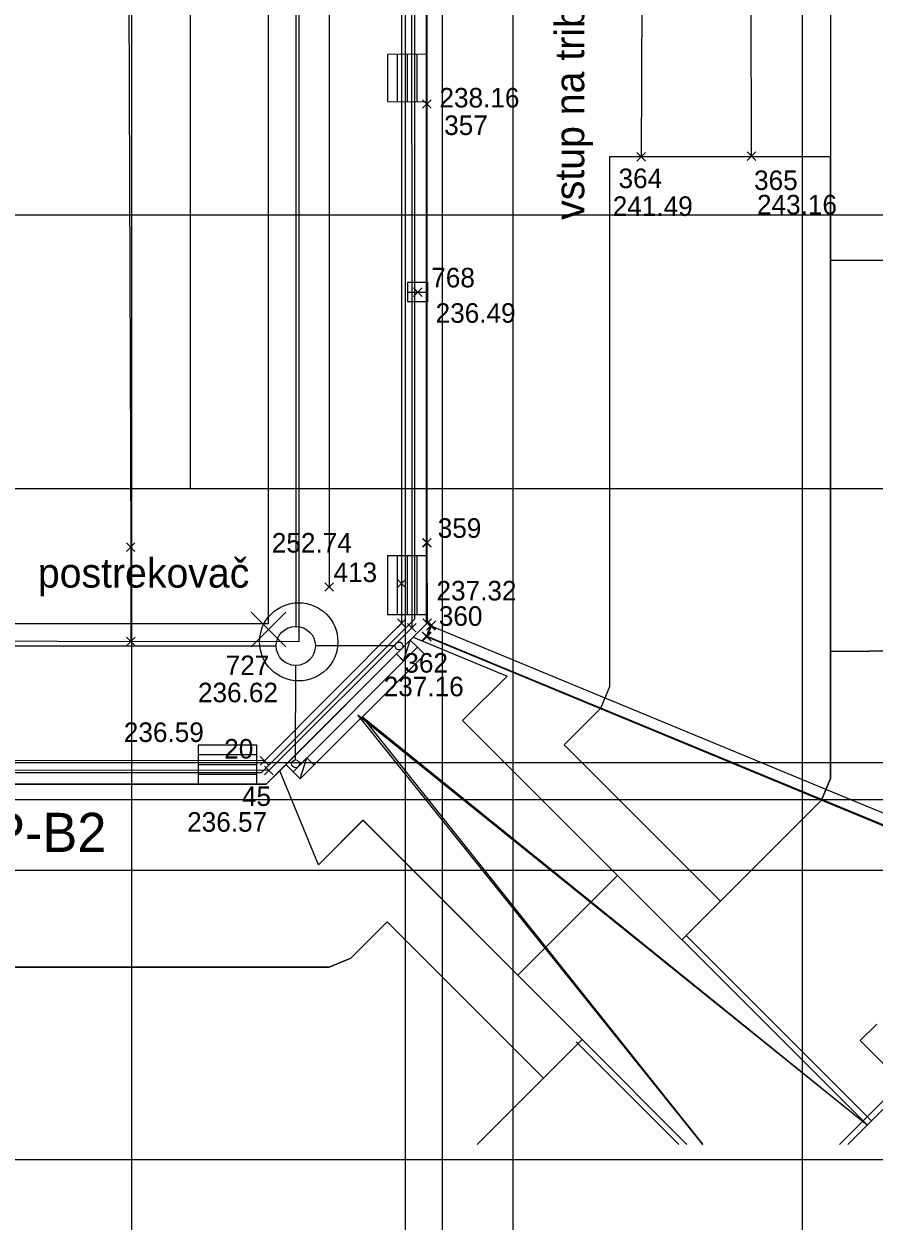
# Model space of a CAD drawing. Extents: x -264205 to -263659, y -1242401 to -1242060.
# Drawn here: x -263822.21 to -263800.48, y -1242235.6 to -1242205 of the extents above; entities that cross this region are included whole.
import ezdxf

# ---------------------------------------------------------------- set-up
doc = ezdxf.new("R2010")
doc.units = 0
for name, color, linetype in [('BOD_CISLO', 7, 'Continuous'), ('BOD_SYMBOL', 7, 'Continuous'), ('BOD_VYSKA', 7, 'Continuous'), ('KFA_SO_10-1_DRENAZNY_SYSTEM_IHRISKA', 7, 'Continuous'), ('KFA_SO_10-1_OBRUBNIKY_IHRISKO', 7, 'Continuous'), ('KFA_SO_10-1_POSTREKOVACE', 7, 'Continuous'), ('KFA_SO_10-1_STRECHY', 7, 'Continuous'), ('KFA_SO_10-1_SVETELNE_VEZE', 7, 'Continuous'), ('KFA_SO_10-1_TRIBUNA_C_OBVOD', 7, 'Continuous'), ('KFA_SO_10-1_VPUST_STADION_POKLOP', 7, 'Continuous'), ('KFA_SO_10-1_VSTUPY_TRIBUNA_C', 7, 'Continuous'), ('KFA_SO_10-1_ZABRADLIE_STADION', 7, 'Continuous'), ('KFA_SO_40-2-II_DAZDOVA_KANALIZACIA', 7, 'Continuous'), ('OBRUBNIKY_KOMUNIKACIE_PROJEKT', 7, 'Continuous'), ('OSI_STAVBY_KFA', 7, 'Continuous'), ('POPIS', 7, 'Continuous'), ('SITUACIA_DSP_2D', 7, 'Continuous')]:
    doc.layers.add(name, color=color, linetype=linetype)

msp = doc.modelspace()

# ---------------------------------------------------------------- linework, layer by layer
at = {"layer": 'BOD_SYMBOL'}
for p, q in [((-263812.024, -1242207.154), (-263811.802, -1242206.933)), ((-263811.802, -1242207.154), (-263812.024, -1242206.933)), ((-263806.545, -1242208.508), (-263806.323, -1242208.286)), ((-263806.323, -1242208.508), (-263806.545, -1242208.286)), ((-263806.541, -1242208.504), (-263806.32, -1242208.282)), ((-263806.32, -1242208.504), (-263806.541, -1242208.282)), ((-263803.72, -1242208.488), (-263803.5, -1242208.266)), ((-263803.5, -1242208.488), (-263803.72, -1242208.266)), ((-263812.257, -1242211.961), (-263812.035, -1242211.741)), ((-263812.035, -1242211.961), (-263812.257, -1242211.741)), ((-263819.595, -1242218.478), (-263819.375, -1242218.257)), ((-263819.375, -1242218.478), (-263819.595, -1242218.257)), ((-263812.02, -1242218.367), (-263811.799, -1242218.147)), ((-263811.799, -1242218.367), (-263812.02, -1242218.147)), ((-263812.019, -1242218.369), (-263811.799, -1242218.147)), ((-263811.799, -1242218.369), (-263812.019, -1242218.147)), ((-263812.67, -1242219.409), (-263812.448, -1242219.188)), ((-263812.448, -1242219.409), (-263812.67, -1242219.188)), ((-263814.522, -1242219.499), (-263814.301, -1242219.279)), ((-263814.301, -1242219.499), (-263814.522, -1242219.279)), ((-263816.072, -1242220.589), (-263815.851, -1242220.367)), ((-263815.851, -1242220.589), (-263816.072, -1242220.367)), ((-263812.667, -1242220.421), (-263812.446, -1242220.2)), ((-263812.446, -1242220.421), (-263812.667, -1242220.2)), ((-263812.406, -1242220.546), (-263812.185, -1242220.326)), ((-263812.185, -1242220.546), (-263812.406, -1242220.326)), ((-263812.018, -1242220.426), (-263811.796, -1242220.204)), ((-263811.796, -1242220.426), (-263812.018, -1242220.204)), ((-263811.921, -1242220.497), (-263811.7, -1242220.275)), ((-263811.7, -1242220.497), (-263811.921, -1242220.275)), ((-263811.904, -1242220.478), (-263811.682, -1242220.258)), ((-263811.682, -1242220.478), (-263811.904, -1242220.258)), ((-263819.59, -1242220.896), (-263819.369, -1242220.674)), ((-263819.369, -1242220.896), (-263819.59, -1242220.674)), ((-263812.03, -1242220.758), (-263811.808, -1242220.536)), ((-263811.808, -1242220.758), (-263812.03, -1242220.536)), ((-263812.024, -1242220.774), (-263811.802, -1242220.552)), ((-263811.802, -1242220.774), (-263812.024, -1242220.552)), ((-263816.175, -1242223.941), (-263815.954, -1242223.72)), ((-263815.954, -1242223.941), (-263816.175, -1242223.72)), ((-263816.066, -1242224.191), (-263815.845, -1242223.97)), ((-263815.845, -1242224.191), (-263816.066, -1242223.97))]:
    msp.add_line(p, q, dxfattribs=at)
at = {"layer": 'KFA_SO_10-1_DRENAZNY_SYSTEM_IHRISKA'}
msp.add_line((-263819.485, -1242218.367), (-263819.48, -1242220.785), dxfattribs=at)
msp.add_lwpolyline([(-263819.808, -1242114.324), (-263819.677, -1242164.565), (-263819.485, -1242218.367)], dxfattribs=at)
at = {"layer": 'KFA_SO_10-1_OBRUBNIKY_IHRISKO'}
msp.add_line((-263812.559, -1242219.298), (-263812.557, -1242220.31), dxfattribs=at)
for points in [[(-263812.554, -1242108.944), (-263812.55, -1242123.834), (-263812.543, -1242140.463), (-263812.561, -1242166.622), (-263812.562, -1242195.738), (-263812.559, -1242219.298)], [(-263812.302, -1242108.944), (-263812.301, -1242123.86), (-263812.298, -1242140.481), (-263812.303, -1242166.591), (-263812.301, -1242195.713), (-263812.296, -1242220.436)], [(-263812.296, -1242220.436), (-263815.955, -1242224.08), (-263837.958, -1242224.073), (-263865.382, -1242224.053), (-263888.004, -1242224.071), (-263891.613, -1242220.398)], [(-263812.557, -1242220.31), (-263816.064, -1242223.83), (-263837.963, -1242223.813), (-263865.333, -1242223.805), (-263887.909, -1242223.807), (-263891.344, -1242220.296)]]:
    msp.add_lwpolyline(points, dxfattribs=at)
at = {"layer": 'KFA_SO_10-1_POSTREKOVACE'}
for p, q in [((-263816.403, -1242220.92), (-263815.519, -1242220.036)), ((-263815.519, -1242220.92), (-263816.403, -1242220.036))]:
    msp.add_line(p, q, dxfattribs=at)
at = {"layer": 'KFA_SO_10-1_STRECHY'}
msp.add_line((-263814.432, -1242109.405), (-263814.411, -1242219.389), dxfattribs=at)
at = {"layer": 'KFA_SO_10-1_TRIBUNA_C_OBVOD'}
msp.add_line((-263795.286, -1242227.548), (-263811.913, -1242220.663), dxfattribs=at)
msp.add_lwpolyline([(-263811.9, -1242108.121), (-263811.778, -1242108.42), (-263811.904, -1242108.455), (-263811.9, -1242110.523), (-263811.9, -1242110.524), (-263811.903, -1242123.046), (-263811.913, -1242144.045), (-263811.917, -1242165.045), (-263811.915, -1242186.053), (-263811.913, -1242207.043), (-263811.91, -1242218.257), (-263811.909, -1242218.258), (-263811.907, -1242220.315), (-263811.793, -1242220.368), (-263811.913, -1242220.663)], dxfattribs=at)
at = {"layer": 'KFA_SO_10-1_VPUST_STADION_POKLOP'}
msp.add_line((-263812.146, -1242211.851), (-263812.146, -1242211.851), dxfattribs=at)
msp.add_lwpolyline([(-263812.396, -1242211.851), (-263812.396, -1242211.601), (-263811.896, -1242211.601), (-263811.896, -1242212.101), (-263812.396, -1242212.101), (-263812.396, -1242211.851), (-263811.896, -1242211.851)], dxfattribs=at)
at = {"layer": 'KFA_SO_10-1_VSTUPY_TRIBUNA_C'}
msp.add_line((-263806.413, -1242204.348), (-263806.434, -1242208.397), dxfattribs=at)
msp.add_lwpolyline([(-263806.434, -1242208.397), (-263806.431, -1242208.393), (-263803.61, -1242208.377), (-263803.618, -1242204.362), (-263806.41, -1242204.343), (-263806.413, -1242204.348)], dxfattribs=at)
at = {"layer": 'KFA_SO_10-1_ZABRADLIE_STADION'}
msp.add_line((-263796.638, -1242226.962), (-263811.919, -1242220.647), dxfattribs=at)
msp.add_lwpolyline([(-263811.919, -1242220.647), (-263811.811, -1242220.386), (-263796.524, -1242226.704), (-263795.888, -1242226.969), (-263796.004, -1242227.229), (-263796.638, -1242226.962)], dxfattribs=at)
at = {"layer": 'KFA_SO_40-2-II_DAZDOVA_KANALIZACIA'}
msp.add_lwpolyline([(-263814.907, -1242107.856), (-263815.198, -1242164.443), (-263815.189, -1242220.791), (-263852.152, -1242220.736), (-263888.701, -1242220.786), (-263906.731, -1242239.259)], dxfattribs=at)
msp.add_circle((-263815.189, -1242220.791), 1, dxfattribs=at)
at = {"layer": 'OBRUBNIKY_KOMUNIKACIE_PROJEKT'}
for p, q in [((-263801.593, -1242104.482), (-263801.593, -1242224.282)), ((-263815.675, -1242224.088), (-263812.262, -1242220.675)), ((-263812.262, -1242220.675), (-263809.863, -1242221.669)), ((-263809.863, -1242221.669), (-263810.999, -1242222.806)), ((-263804.857, -1242233.636), (-263813.678, -1242222.657)), ((-263813.678, -1242222.657), (-263800.652, -1242233.141)), ((-263810.999, -1242222.806), (-263805.392, -1242228.407)), ((-263814.681, -1242226.488), (-263815.675, -1242224.088)), ((-263801.593, -1242224.282), (-263801.824, -1242224.838)), ((-263801.824, -1242224.838), (-263805.392, -1242228.407)), ((-263813.544, -1242225.352), (-263814.681, -1242226.488)), ((-263807.941, -1242230.956), (-263813.544, -1242225.352)), ((-263794.893, -1242227.382), (-263801.147, -1242233.636)), ((-263805.283, -1242228.297), (-263800.546, -1242233.035)), ((-263805.389, -1242228.403), (-263800.652, -1242233.141)), ((-263807.941, -1242230.956), (-263810.622, -1242233.636)), ((-263808.093, -1242231.016), (-263805.473, -1242233.636)), ((-263807.987, -1242230.91), (-263805.261, -1242233.636))]:
    msp.add_line(p, q, dxfattribs=at)
at = {"layer": 'OSI_STAVBY_KFA'}
for p, q in [((-263819.468, -1242083.237), (-263819.468, -1242246.707)), ((-263812.468, -1242083.237), (-263812.468, -1242246.707)), ((-263811.518, -1242083.237), (-263811.518, -1242246.707)), ((-263809.718, -1242083.237), (-263809.718, -1242246.707)), ((-263802.318, -1242083.237), (-263802.318, -1242246.707)), ((-263792.653, -1242209.882), (-263909.343, -1242209.882)), ((-263792.653, -1242216.882), (-263911.523, -1242216.882)), ((-263792.653, -1242223.882), (-263911.523, -1242223.882)), ((-263792.653, -1242224.832), (-263911.523, -1242224.832)), ((-263792.653, -1242226.632), (-263911.523, -1242226.632)), ((-263792.653, -1242234.032), (-263911.523, -1242234.032))]:
    msp.add_line(p, q, dxfattribs=at)
at = {"layer": 'SITUACIA_DSP_2D'}
for p, q in [((-263801.593, -1242104.482), (-263801.593, -1242224.282)), ((-263815.968, -1242108.434), (-263815.968, -1242220.33)), ((-263811.918, -1242108.434), (-263811.918, -1242220.33)), ((-263811.918, -1242220.33), (-263811.918, -1242108.434)), ((-263812.218, -1242220.206), (-263812.218, -1242108.558)), ((-263817.968, -1242111.882), (-263817.968, -1242216.882)), ((-263815.263, -1242164.687), (-263815.263, -1242220.396)), ((-263811.924, -1242205.773), (-263812.918, -1242205.782)), ((-263812.918, -1242205.782), (-263812.918, -1242206.982)), ((-263812.668, -1242205.782), (-263812.668, -1242206.982)), ((-263812.418, -1242205.782), (-263812.418, -1242206.982)), ((-263812.168, -1242205.782), (-263812.168, -1242206.982)), ((-263812.918, -1242206.982), (-263811.924, -1242206.991)), ((-263807.243, -1242208.394), (-263807.243, -1242221.942)), ((-263801.593, -1242208.394), (-263807.243, -1242208.394)), ((-263801.593, -1242208.394), (-263807.243, -1242208.394)), ((-263807.243, -1242208.394), (-263807.243, -1242221.942)), ((-263801.593, -1242224.282), (-263801.593, -1242208.394)), ((-263801.593, -1242224.282), (-263801.593, -1242208.394)), ((-263801.593, -1242211.032), (-263800.593, -1242211.032)), ((-263800.593, -1242211.032), (-263793.136, -1242211.032)), ((-263817.968, -1242216.882), (-263885.968, -1242216.882)), ((-263811.939, -1242218.592), (-263812.918, -1242218.592)), ((-263812.918, -1242218.592), (-263812.918, -1242220.092)), ((-263812.668, -1242218.592), (-263812.668, -1242220.092)), ((-263812.418, -1242218.592), (-263812.418, -1242220.092)), ((-263812.168, -1242218.592), (-263812.168, -1242220.092)), ((-263812.918, -1242220.092), (-263811.918, -1242220.092)), ((-263815.968, -1242220.33), (-263887.968, -1242220.33)), ((-263816.144, -1242224.132), (-263812.218, -1242220.206)), ((-263816.02, -1242224.432), (-263811.918, -1242220.33)), ((-263811.918, -1242220.33), (-263812.262, -1242220.675)), ((-263815.675, -1242224.088), (-263812.262, -1242220.675)), ((-263812.262, -1242220.675), (-263809.862, -1242221.669)), ((-263812.262, -1242220.675), (-263809.863, -1242221.669)), ((-263851.668, -1242220.896), (-263815.763, -1242220.896)), ((-263815.516, -1242223.929), (-263812.335, -1242220.747)), ((-263815.334, -1242224.112), (-263812.152, -1242220.929)), ((-263812.725, -1242220.896), (-263814.763, -1242220.896)), ((-263812.506, -1242221.283), (-263812.335, -1242220.747)), ((-263812.151, -1242220.931), (-263812.335, -1242220.747)), ((-263811.968, -1242221.113), (-263812.152, -1242220.929)), ((-263801.593, -1242221.032), (-263800.593, -1242221.032)), ((-263788.893, -1242221.032), (-263800.593, -1242221.032)), ((-263811.968, -1242221.113), (-263815.15, -1242224.295)), ((-263812.504, -1242221.284), (-263812.688, -1242221.101)), ((-263815.27, -1242223.809), (-263815.264, -1242221.396)), ((-263809.862, -1242221.669), (-263810.999, -1242222.806)), ((-263809.863, -1242221.669), (-263810.999, -1242222.806)), ((-263807.243, -1242221.942), (-263807.472, -1242222.496)), ((-263807.243, -1242221.942), (-263807.472, -1242222.496)), ((-263807.472, -1242222.496), (-263808.4, -1242223.424)), ((-263807.472, -1242222.496), (-263808.4, -1242223.424)), ((-263804.844, -1242233.636), (-263813.559, -1242222.704)), ((-263813.559, -1242222.704), (-263800.652, -1242233.141)), ((-263810.999, -1242222.806), (-263807.039, -1242226.765)), ((-263810.999, -1242222.806), (-263805.392, -1242228.407)), ((-263816.259, -1242223.432), (-263817.757, -1242223.432)), ((-263817.757, -1242223.432), (-263817.757, -1242224.432)), ((-263816.259, -1242224.432), (-263816.259, -1242223.432)), ((-263808.4, -1242223.424), (-263804.405, -1242227.419)), ((-263808.4, -1242223.424), (-263804.405, -1242227.419)), ((-263816.259, -1242223.682), (-263817.757, -1242223.682)), ((-263815.15, -1242224.295), (-263814.98, -1242223.758)), ((-263814.797, -1242223.942), (-263814.98, -1242223.758)), ((-263816.259, -1242223.932), (-263817.757, -1242223.932)), ((-263815.675, -1242224.088), (-263816.02, -1242224.432)), ((-263814.681, -1242226.488), (-263815.675, -1242224.088)), ((-263814.681, -1242226.488), (-263815.675, -1242224.088)), ((-263815.333, -1242224.113), (-263815.516, -1242223.929)), ((-263887.792, -1242224.132), (-263816.144, -1242224.132)), ((-263816.259, -1242224.182), (-263817.757, -1242224.182)), ((-263815.15, -1242224.295), (-263815.334, -1242224.112)), ((-263801.593, -1242224.282), (-263801.824, -1242224.838)), ((-263801.822, -1242224.837), (-263801.593, -1242224.282)), ((-263801.822, -1242224.837), (-263801.593, -1242224.282)), ((-263816.02, -1242224.432), (-263887.916, -1242224.432)), ((-263887.916, -1242224.432), (-263816.02, -1242224.432)), ((-263801.824, -1242224.838), (-263805.392, -1242228.407)), ((-263804.405, -1242227.419), (-263801.822, -1242224.837)), ((-263804.405, -1242227.419), (-263801.822, -1242224.837)), ((-263813.545, -1242225.351), (-263814.681, -1242226.488)), ((-263813.544, -1242225.352), (-263814.681, -1242226.488)), ((-263809.585, -1242229.311), (-263813.545, -1242225.351)), ((-263807.941, -1242230.956), (-263813.544, -1242225.352)), ((-263807.039, -1242226.765), (-263809.585, -1242229.311)), ((-263794.893, -1242227.382), (-263801.147, -1242233.636)), ((-263795.272, -1242227.55), (-263801.359, -1242233.636)), ((-263812.926, -1242227.95), (-263813.854, -1242228.878)), ((-263813.854, -1242228.878), (-263812.926, -1242227.95)), ((-263808.931, -1242231.945), (-263812.926, -1242227.95)), ((-263812.926, -1242227.95), (-263808.931, -1242231.945)), ((-263805.283, -1242228.297), (-263800.546, -1242233.035)), ((-263805.389, -1242228.403), (-263800.652, -1242233.141)), ((-263813.854, -1242228.878), (-263814.408, -1242229.107)), ((-263814.408, -1242229.107), (-263813.854, -1242228.878)), ((-263814.408, -1242229.107), (-263828.955, -1242229.107)), ((-263828.955, -1242229.107), (-263814.408, -1242229.107)), ((-263800.834, -1242230.985), (-263800.41, -1242230.561)), ((-263807.942, -1242230.956), (-263810.622, -1242233.636)), ((-263808.093, -1242231.016), (-263805.473, -1242233.636)), ((-263807.987, -1242230.91), (-263805.261, -1242233.636)), ((-263799.774, -1242232.046), (-263800.834, -1242230.985)), ((-263810.622, -1242233.636), (-263808.931, -1242231.945)), ((-263808.931, -1242231.945), (-263810.622, -1242233.636))]:
    msp.add_line(p, q, dxfattribs=at)
for points in [[(-263812.688, -1242221.101), (-263812.506, -1242221.283), (-263812.335, -1242220.747)], [(-263814.98, -1242223.758), (-263815.334, -1242224.112), (-263815.15, -1242224.295)]]:
    msp.add_lwpolyline(points, close=True, dxfattribs=at)
for centre, radius in [((-263815.263, -1242220.896), 0.5), ((-263812.625, -1242220.896), 0.1), ((-263815.27, -1242223.909), 0.1)]:
    msp.add_circle(centre, radius, dxfattribs=at)

# ---------------------------------------------------------------- texts
at = {"layer": 'BOD_CISLO'}
for s, p in [('357', (-263811.469, -1242207.836)), ('364', (-263807.011, -1242209.194)), ('365', (-263803.546, -1242209.242)), ('768', (-263811.8, -1242211.731)), ('359', (-263811.634, -1242218.133)), ('413', (-263814.3, -1242219.264)), ('360', (-263811.606, -1242220.382)), ('727', (-263817.056, -1242221.642)), ('362', (-263812.488, -1242221.578)), ('20', (-263817.093, -1242223.775)), ('45', (-263816.64, -1242224.986))]:
    msp.add_text(s, height=0.5, dxfattribs=at).set_placement(p)
at = {"layer": 'BOD_VYSKA'}
for s, p in [('238.16', (-263811.59, -1242207.133)), ('241.49', (-263807.159, -1242209.905)), ('243.16', (-263803.471, -1242209.866)), ('236.49', (-263811.688, -1242212.636)), ('252.74', (-263815.876, -1242218.51)), ('237.32', (-263811.666, -1242219.733)), ('236.62', (-263817.764, -1242222.336)), ('237.16', (-263813.015, -1242222.183)), ('236.59', (-263819.66, -1242223.351)), ('236.57', (-263818.041, -1242225.645))]:
    msp.add_text(s, height=0.5, dxfattribs=at).set_placement(p)
at = {"layer": 'KFA_SO_10-1_SVETELNE_VEZE'}
msp.add_text('UDO18P-B2', height=1, dxfattribs=at).set_placement((-263827.537, -1242226.162))
at = {"layer": 'POPIS'}
msp.add_text('vstup na tribúnu', height=0.75, rotation=90, dxfattribs=at).set_placement((-263807.889, -1242210.006))
msp.add_text('postrekovač', height=0.75, dxfattribs=at).set_placement((-263821.858, -1242219.405))

doc.saveas('drawing.dxf')
